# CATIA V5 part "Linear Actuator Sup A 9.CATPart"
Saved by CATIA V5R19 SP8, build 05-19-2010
Part number: Linear Actuator Sup A 9
Publications: "Diamètre Linear Actuator Sup A", "Rayon Linear Actuator Sup A"
Bounding box of the stored display mesh (mm): x -29.961 to 29.961, y -10 to 180, z 720.039 to 779.961
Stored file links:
  G:\EU_thinkMotion\CFAO_2010\MMS_groupe3\MMS_groupe3\A reprendre\fovide\fovide\Linear Actuator Sup A 9.CATPart
  G:\EU_thinkMotion\CFAO_2010\MMS_groupe3\MMS_groupe3\A reprendre\fovide\fovide\fovide.CATProduct
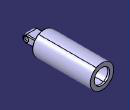
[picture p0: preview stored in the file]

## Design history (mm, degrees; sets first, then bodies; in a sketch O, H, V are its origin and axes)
Parameters
  `Diamètre Linear Actuator Sup A` = 60 mm
  `Rayon Linear Actuator Sup A` = 30 mm {= `Diamètre Linear Actuator Sup A` /2}
Set1
  Plane1: linked copy from another document
  Point1 "Point.A": linked copy from another document
  Line1: linked copy from another document
  Line2: linked copy from another document
Body1 (main body)
  Sketch1 on Plane1, origin (0, 0, 0), H (0, 1, 0), V (0, 0, 1)
    arc A1 centre (0, 750) radius 10 from (0, 760) to (0, 740) ccw
    point P1 (0, 750)
    point P2 (0, 760)
    point P3 (0, 740)
    reference projected point E1 (0, 750) from Point1
    line L1 (0, 760) -> (30, 760)
    line L2 (30, 760) -> (30, 740)
    line L3 (30, 740) -> (0, 740)
    point P6 (0, 740)
    radius A1 = 10
    length L1 = 30
    coincidence: P2 V, P3 V, P1 E1, P6 P3
    horizontal: L1 H, L3 H
    vertical: L2 V
  Pad1: profile Sketch1, direction (1, 0, 0), length 15, mirrored extent
  Sketch2 on end face of Pad1, origin (15, 0, 750), H (0, 1, 0), V (0, 0, 1)
    point P1 (0, 0)
    intersected point E1 (0, 0) from Line2
    coincidence: E1 P1
  Hole1: placed by Sketch2, at (15, 0, 750) direction (-1, 0, 0), diameter 10 {= `Rayon Linear Actuator Sup A` /3}, through (limit type 6)
  Sketch3 on Plane1, origin (0, 0, 0), H (0, 1, 0), V (0, 0, 1)
    line L1 (30, 750) -> (30, 780)
    line L2 (30, 780) -> (180, 780)
    line L3 (180, 780) -> (180, 770)
    line L4 (180, 770) -> (175, 770)
    line L5 (175, 770) -> (175, 775)
    line L6 (175, 775) -> (40, 775)
    line L7 (40, 775) -> (40, 750)
    line L8 (40, 750) -> (30, 750)
    reference projected line E1 (0, 750) -> (450, 750) from Line1
    reference projected line E2 (30, 740) -> (30, 760) from edge [face of Pad1 from Sketch1.L2 | end face of Pad1]
    length L1 = 30 {= `Rayon Linear Actuator Sup A`}
    length L2 = 150
    length L7 = 25 {= `Rayon Linear Actuator Sup A` *5/6}
    distance L7 L1 = 10 {= `Rayon Linear Actuator Sup A` /3}
    length L5 = 5 {= `Rayon Linear Actuator Sup A` /6}
    length L4 = 5 {= `Rayon Linear Actuator Sup A` /6}
    vertical: L1 V, L3 V, L5 V, L7 V
    horizontal: L2 H, L4 H, L6 H, L8 H
    coincidence: L8 E1, L1 E2
  Shaft1: profile Sketch3, axis Line1, angle 360
  Fillet1: radius 2, on face of Shaft1 from Sketch3.L1; end face of Pad1; start face of Pad1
